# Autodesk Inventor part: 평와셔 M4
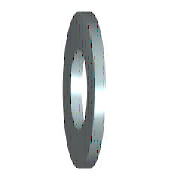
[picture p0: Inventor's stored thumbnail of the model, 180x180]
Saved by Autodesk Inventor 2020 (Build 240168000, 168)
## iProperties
Created: 2012-02
Part Number: 평와셔 M4
Material: 스테인리스강
Description: 평면 와셔 - 일반 시리즈 - 제품 등급 A
Document SubType Name: Modeling
Standard: ISO 7089
Designer: mdu-01
Standard Revision: Second edition 2000-06-01
Standards Organization: ISO
Language: ko-KR
Size Designation: 4 - 140 HV
Categories: <MemberInstance><Categories><Category DisplayName="조임쇠" InternalName="e4da775c-781d-43d5-af7c-5136215cf5a6" Mnemonic="FSTN"><Category DisplayName="와셔" InternalN
Density: 8.08 g/cm^3
Appearance: 반광택
IsCustomPart: 1
Author: mdu-01
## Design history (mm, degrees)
sketch "스케치"
  geometry: C1 r 4.5 at (0, 0); C2 r 2.15 at (0, 0); 1 further point
  constraints: 2 centre point, 2 coincident
  dimensions: "d0" = 4.3 diameter of C2 (= SD1); "d1" = 9 diameter of C1 (= SD2)
extrude "본체" new body sketch "스케치" distance "d2" = 0.8 (= SD); taper "d3" = 0 deg
workaxis "Work Axis1"
workplane "Work Plane1"
body "Solid1"
other parameters: "SD1" = 4.3 [user parameter; used in 1 equation term], "SD2" = 9 [user parameter; used in 1 equation term], "SD" = 0.8 [user parameter; used in 1 equation term], "d4" = 0, "d5" = 0, "d6" = 0, "d7" = 0, "NND" = 4 [user parameter]
